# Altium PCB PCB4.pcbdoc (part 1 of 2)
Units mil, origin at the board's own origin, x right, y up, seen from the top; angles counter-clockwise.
Board outline 2271.98 x 2855.49 mil, 2 copper layers (Top Layer, Bottom Layer); 93 components, 70 nets, 333 pads, 163 vias.
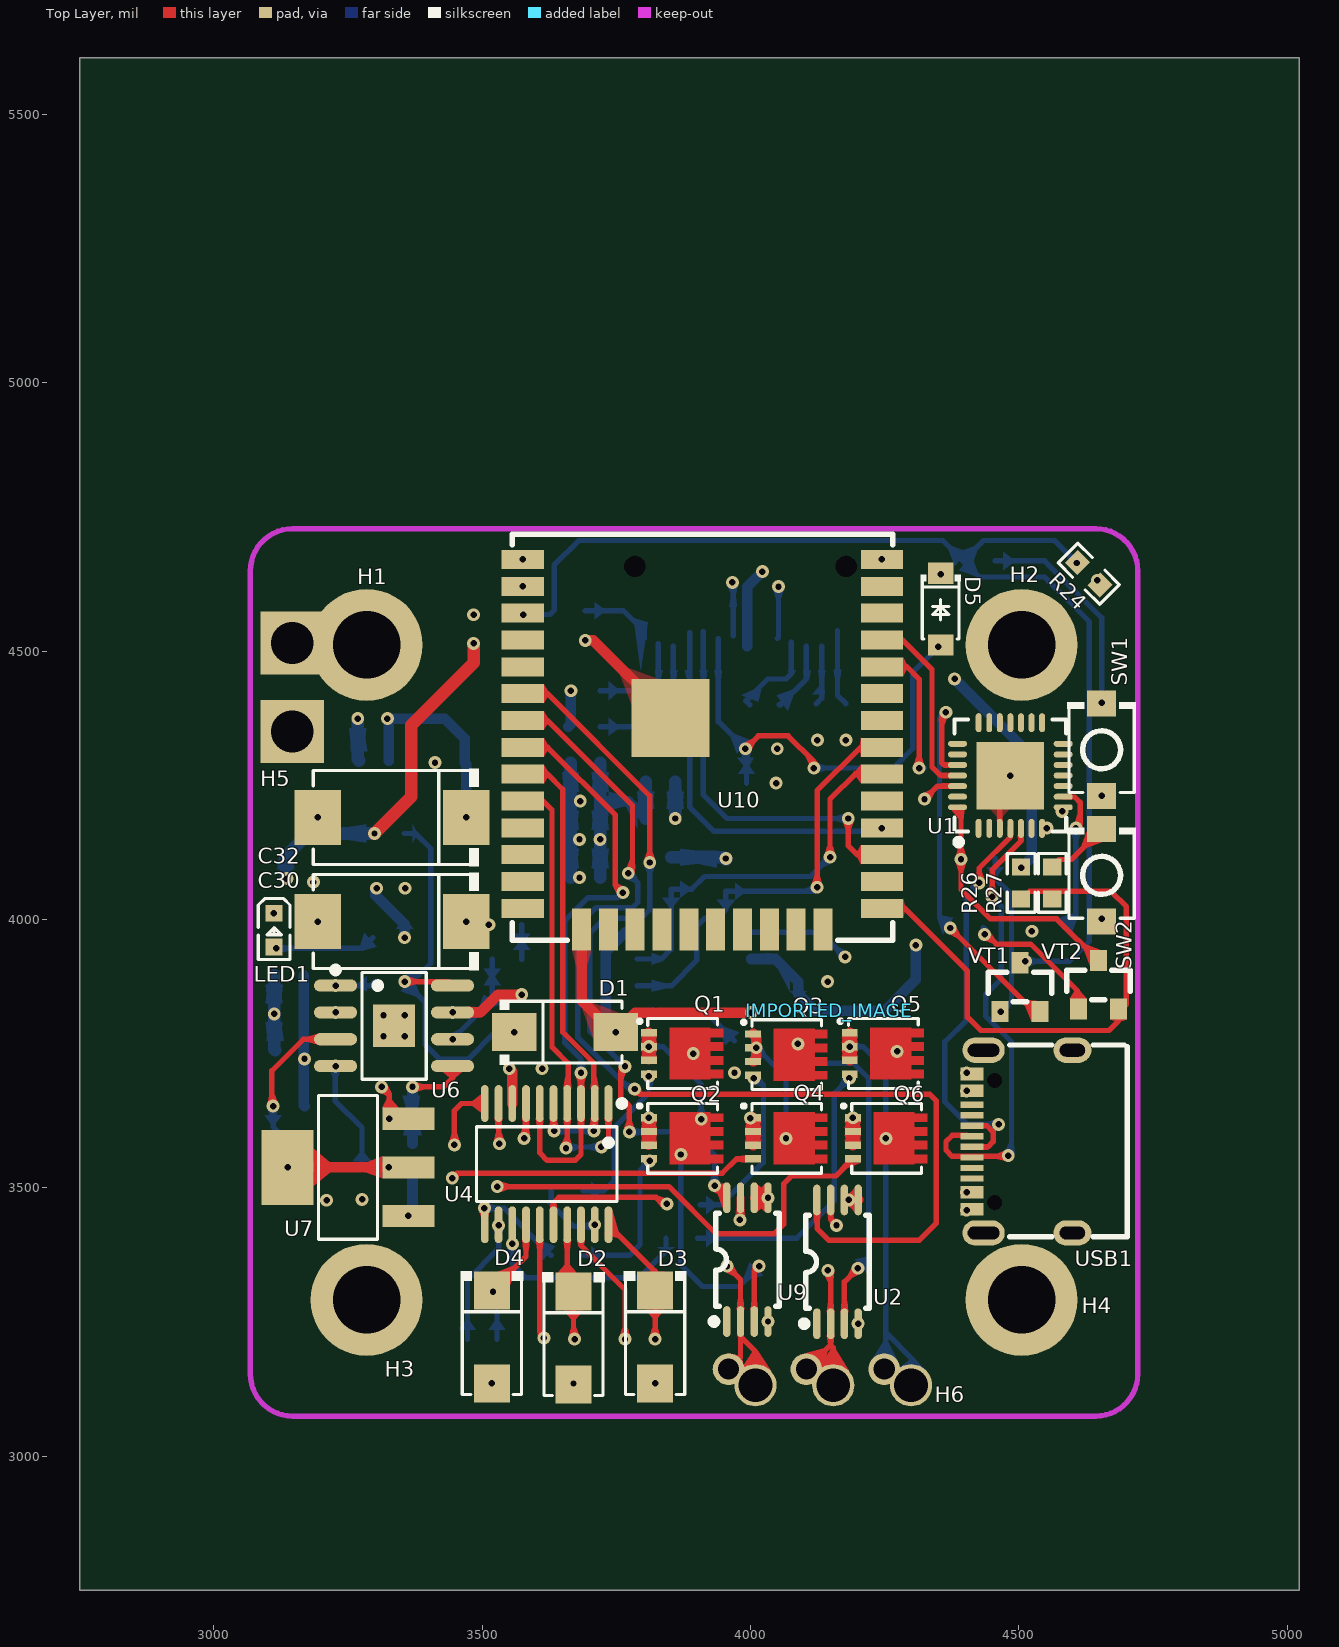
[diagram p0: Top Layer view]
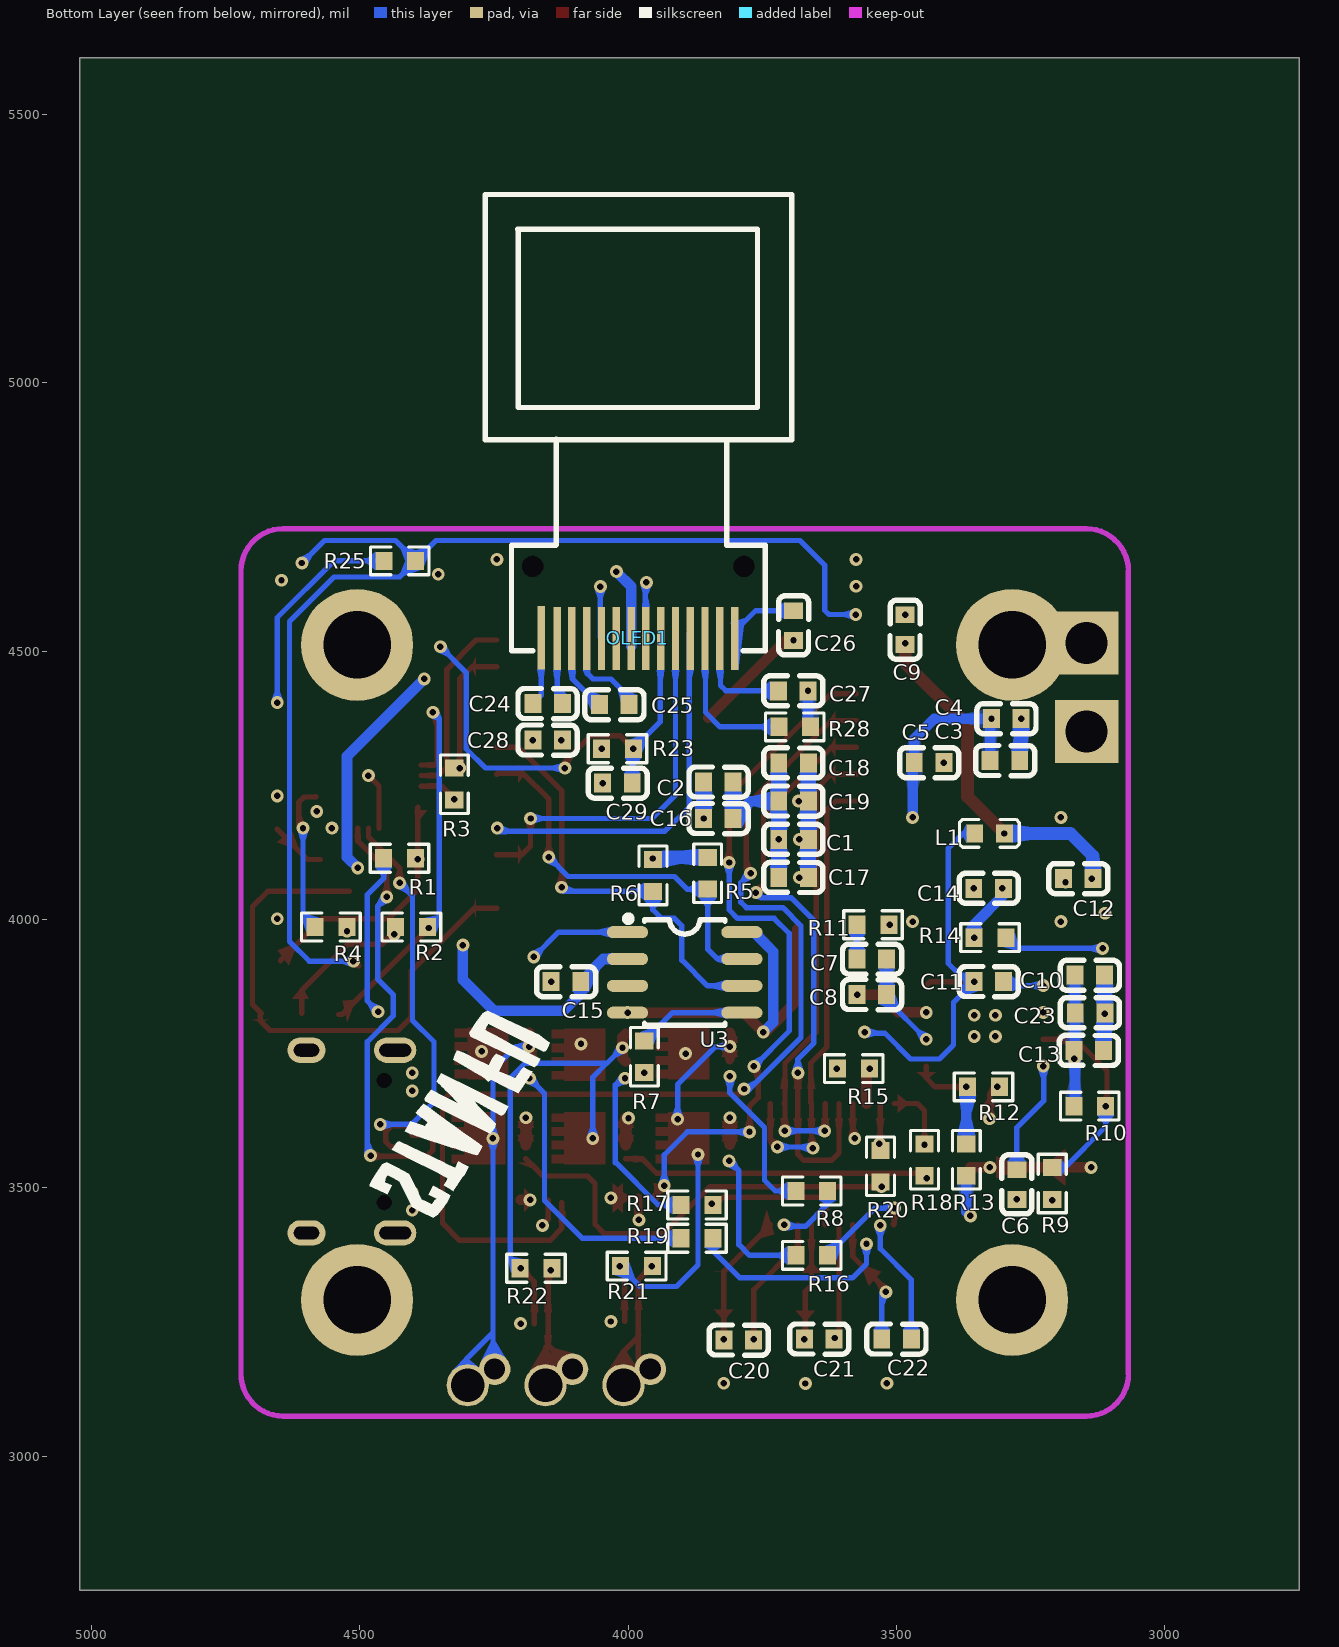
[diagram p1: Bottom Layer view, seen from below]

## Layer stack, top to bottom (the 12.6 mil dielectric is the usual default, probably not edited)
Top Layer: signal copper (thickness not stored)
Dielectric: dielectric 12.6, FR-4, Dk 4.8
Bottom Layer: signal copper (thickness not stored)

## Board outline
5021.98,2750 2750,2750 2750,5605.49 5021.98,5605.49

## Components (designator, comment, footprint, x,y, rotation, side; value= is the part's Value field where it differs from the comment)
C1 "0603B104K500NT_C30926" C0603 3692,4149.18 r180 bottom
C2 "0603B104K500NT_C30926" C0603 3832,4256 r0 bottom
C3 "CAP_0603" C0603 3298,4296 r0 bottom
C4 "CAP_0603" C0603 3295.56,4374 r0 bottom
C5 "CAP_0603" C0603 3439.56,4292 r0 bottom
C6 "CAP_0603" C0603 3276,3506 r270 bottom
C7 "CAP_0603" C0603 3546,3926 r0 bottom
C8 "CAP_0603" C0603 3546,3860 r0 bottom
C9 "CAP_0603" C0603 3484,4540 r90 bottom
C10 "CAP_0603" C0603 3140,3896 r0 bottom
C11 "CAP_0603" C0603 3328,3884 r180 bottom
C12 "CAP_0603" C0603 3161.56,4076 r0 bottom
C13 "CAP_0603" C0603 3142,3756 r0 bottom
C14 "CAP_0603" C0603 3328.61,4058 r0 bottom
C15 "CAP_0603" C0603 4116,3884 r0 bottom
C16 "0603B104K500NT_C30926" C0603 3832,4188 r0 bottom
C17 "0603B104K500NT_C30926" C0603 3692,4078 r180 bottom
C18 "0603B104K500NT_C30926" C0603 3692,4291.54 r180 bottom
C19 "0603B104K500NT_C30926" C0603 3692,4220.36 r180 bottom
C20 "CAP_0603" C0603 3794,3216 r180 bottom
C21 "CAP_0603" C0603 3644,3218 r180 bottom
C22 "CAP_0603" C0603 3500,3218 r180 bottom
C23 "CAP_0603" C0603 3139.56,3826 r180 bottom
C24 "CAP_0603" C0603 4150,4402 r180 bottom
C25 "CAP_0603" C0603 4026,4400 r0 bottom
C26 "CAP_0603" C0603 3692,4547.56 r270 bottom
C27 "CAP_0603" C0603 3692.61,4426 r0 bottom
C28 "CAP_0603" C0603 4150,4334 r180 bottom
C29 "CAP_0603" C0603 4020,4254 r0 bottom
C30 "TAJE107M025RNJ" CAP-SMD_L7.3-W4.3-R-RD 3332,3996 r0 top
C32 "TAJE107M025RNJ" CAP-SMD_L7.3-W4.3-R-RD 3332,4190 r0 top
D1 "SS34_C3014011" SMA_L4.3-W2.7-LS5.1-RD 3654,3790 r0 top
D2 "1N5819_C437199" SMA_L4.4-W2.6-LS5.0-RD 3670,3220 r270 top
D3 "1N5819_C437199" SMA_L4.4-W2.6-LS5.0-RD 3822,3222 r270 top
D4 "1N5819_C437199" SMA_L4.4-W2.6-LS5.0-RD 3518,3222 r270 top
D5 "1N4148W_C129869" SOD-123_L2.6-W1.8-LS3.7-RD 4354,4578 r270 top
H1 "M3定位孔" M3定位孔 3284.54,4511.46 r0 top
H2 "M3定位孔" M3定位孔 4505.01,4511.46 r0 top
H3 "M3定位孔" M3定位孔 3284.54,3290.99 r0 top
H4 "M3定位孔" M3定位孔 4505.01,3290.99 r0 top
H5 "Power Hole" "POWER IN" 3146,4350 r180 top
H6 "Motor Output Hole" "Motor Output Pin" 4008.92,3132.08 r90 top
IMPORTED_IMAGE "IMPORTED_IMAGE" IMPORTED_IMAGE 4146.34,3830.01 r0 top
L1 "L_0603" L0603 3326.81,4160 r180 bottom
LED1 "NCD0603R1_C84263" LED0603-RD_RED 3112,3980 r270 top
OLED1 "QG-6432TLBEG02" OLED-SMD_QG-6432TLBEG02 3982,4524 r270 bottom
Q1 "WSD3066DN33" DFN-8_L3.3-W3.3-P0.65-BL 3841.31,3750.09 r270 top
Q2 "WSD3066DN33" DFN-8_L3.3-W3.3-P0.65-BL 3841.31,3592.09 r270 top
Q3 "WSD3066DN33" DFN-8_L3.3-W3.3-P0.65-BL 4035.31,3748.09 r270 top
Q4 "WSD3066DN33" DFN-8_L3.3-W3.3-P0.65-BL 4035.31,3592.09 r270 top
Q5 "WSD3066DN33" DFN-8_L3.3-W3.3-P0.65-BL 4215.31,3750.09 r270 top
Q6 "WSD3066DN33" DFN-8_L3.3-W3.3-P0.65-BL 4221.31,3592.09 r270 top
R1 "0603WAF1002T5E" R0603 4426,4114 r0 bottom
R2 "0603WAF1002T5E" R0603 4404,3986 r0 bottom
R3 "0603WAF1002T5E" R0603 4324,4252 r270 bottom
R4 "0603WAF1002T5E" R0603 4554,3986 r0 bottom
R5 "0603WAF1002T5E" R0603 3852,4086 r270 bottom
R6 "0603WAF1002T5E" R0603 3954,4082 r270 bottom
R7 "0603WAF1002T5E" R0603 3970,3744 r270 bottom
R8 "0603WAF1002T5E" R0603 3658,3494 r180 bottom
R9 "Res_0603" R0603 3210,3508 r270 bottom
R10 "Res_0603" R0603 3140,3652 r180 bottom
R11 "Res_0603" R0603 3544,3990 r0 bottom
R12 "Res_0603" R0603 3338,3688 r180 bottom
R13 "Res_0603" R0603 3370,3552 r90 bottom
R14 "Res_0603" R0603 3325.81,3966 r180 bottom
R15 "Res_0603" R0603 3580,3722 r180 bottom
R16 "0603WAF1002T5E" R0603 3658,3374 r180 bottom
R17 "0603WAF1002T5E" R0603 3872,3468 r180 bottom
R18 "0603WAF1002T5E" R0603 3448,3552 r90 bottom
R19 "0603WAF1002T5E" R0603 3872,3406 r180 bottom
R20 "0603WAF1002T5E" R0603 3530,3540 r90 bottom
R21 "Res_0603" R0603 3984.34,3354 r0 bottom
R22 "Res_0603" R0603 4172,3350 r0 bottom
R23 "Res_0603" R0603 4020,4318 r0 bottom
R24 "Res_0603" R0603 4630,4644 r315 top
R25 "Res_0603" R0603 4425.66,4668 r180 bottom
R26 "Res_0603" R0603 4504,4068 r90 top
R27 "Res_0603" R0603 4562,4068 r270 top
R28 "Res_0603" R0603 3689.81,4358.77 r0 bottom
SW1 "TS-1088-AR02016" SW-SMD_L3.9-W3.0-P4.45 4654,4316 r90 top
SW2 "TS-1088-AR02016" SW-SMD_L3.9-W3.0-P4.45 4654,4082 r90 top
U1 "CP2102-GMR" WQFN-28_L5.0-W5.0-P0.50-BL-EP3.2 4484.01,4268.01 r0 top
U2 "INA240A2PWR" TSSOP-8_L4.4-W3.0-P0.65-LS6.4-BL 4162,3362 r0 top
U3 "AS5600-ASOT" SOIC-8_L5.0-W4.0-P1.27-LS6.0-BL 3894.77,3901.23 r270 bottom
U4 "EG2133_C190343" TSSOP-20_L6.5-W4.4-P0.65-LS6.4-BL 3620,3544 r180 top
U6 "TPS54331DDAR" SOIC-8_L5.0-W4.0-P1.27-LS6.0-BL-EP2.0 3335.68,3801.68 r270 top
U7 "AMS1117-3.3_C351785" SOT-223_L6.5-W3.5-P2.30-LS7.0-BR 3250,3538 r0 top
U9 "INA240A2PWR" TSSOP-8_L4.4-W3.0-P0.65-LS6.4-BL 3994,3366 r0 top
U10 "ESP32-WROOM-32U-H4" WIFI-SMD_ESP32-WROOM-32UE-A 3910,4326 r0 top
USB1 "TYPE-C 16PIN 2MD(073)" USB-C-SMD_TYPE-C-6PIN-2MD-073 4506,3586 r90 top
VT1 "S8050_C397180" SOT-23_L2.9-W1.3-P1.90-LS2.4-BR 4502,3874 r270 top
VT2 "S8050_C397180" SOT-23_L2.9-W1.3-P1.90-LS2.4-BR 4648,3878 r270 top

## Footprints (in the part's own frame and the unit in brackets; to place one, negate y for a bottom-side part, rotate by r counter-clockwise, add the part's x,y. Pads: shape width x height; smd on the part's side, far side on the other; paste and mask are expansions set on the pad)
C0603 [mm]
  rect 0.8x0.9 smd: 1(-0.7,0) 2(0.7,0)
  silkscreen extent -1.41,-0.71 1.39,0.72
CAP-SMD_L7.3-W4.3-R-RD [mil]
  rect 86.91x102.05 smd: 1(138.24,0) 2(-138.24,0)
  silkscreen extent -147,-91 162,91
DFN-8_L3.3-W3.3-P0.65-BL [mm]
  rect 0.35x0.75 smd: 1(-0.975,-0.78) 2(-0.325,-0.78) 3(0.325,-0.78) 4(0.975,-0.78)
  Top Layer region: -1.222,0.201 -1.222,2.129 -1.174,2.129 -1.174,2.73 -0.773,2.73 -0.773,2.129 -0.524,2.129 -0.524,2.73 -0.123,2.73 -0.123,2.129 0.126,2.129 0.126,2.73 0.528,2.73 0.528,2.129 0.777,2.129 0.777,2.73 0.777,2.129 0.777,2.73 1.178,2.73 1.178,2.129 1.226,2.129 1.226,0.201
  silkscreen extent -1.65,-1.27 1.65,2.46
IMPORTED_IMAGE [mil]
L0603 [mm]
  rect 0.8x0.864 smd: 1(-0.7,0) 2(0.7,0)
  silkscreen extent -1.42,-0.65 1.41,0.67
LED0603-RD_RED [mm]
  rect 0.8x0.8 smd: 1(-0.8,-0.003) 2(0.8,0.003)
  silkscreen extent -1.49,-0.75 1.39,0.76
M3定位孔 [mm]
  round 5.3 hole 3.2: 1(0,0)
"Motor Output Pin" [mm]
  round 2 hole 1.6: 1(0,0) 2(-0.002,-3.685) 3(-0.002,-7.368)
  round 1.5 hole 1: 1(0.762,1.27) 2(0.76,-2.415) 3(0.76,-6.098)
OLED-SMD_QG-6432TLBEG02 [mm]
  rect 3x0.35 smd: 1(-0.017,-4.577) 2(0.017,-3.823) 3(0.017,-3.122) 4(0.017,-2.423) 5(0.017,-1.722) 6(0.017,-1.024) 7(0.017,-0.323) 8(0.017,0.378) 9(0.017,1.077) 10(0.017,1.778) 11(0.017,2.476) 12(0.017,3.178) 13(0.017,3.879) 14(0.017,4.577)
  Multi-Layer board cut-out: -3.398,4.519 -3.614,4.569 -3.788,4.707 -3.885,4.908 -3.885,5.13 -3.788,5.331 -3.614,5.47 -3.398,5.519 -3.398,5.519 -3.181,5.47 -3.007,5.331 -2.91,5.13 -2.91,4.908 -3.007,4.707 -3.181,4.569 -3.398,4.519
  Multi-Layer board cut-out: -3.398,-5.481 -3.614,-5.431 -3.788,-5.293 -3.885,-5.092 -3.885,-4.87 -3.788,-4.669 -3.614,-4.53 -3.398,-4.481 -3.398,-4.481 -3.181,-4.53 -3.007,-4.669 -2.91,-4.87 -2.91,-5.092 -3.007,-5.293 -3.181,-5.431 -3.398,-5.481
  silkscreen extent -21,-7.22 0.6,7.28
"POWER IN" [mm]
  rect 3x3 hole 2: 1(0,0) 2(0,-4.191)
R0603 [mil]
  rect 31.75x34.02 smd: 1(-29.66,0) 2(29.66,0)
  silkscreen extent -55,-26 55,26
SMA_L4.3-W2.7-LS5.1-RD [mm]
  rect 2.1x1.8 smd: 1(-2.4,0) 2(2.4,0)
  silkscreen extent -3.08,-1.54 2.7,1.54
SMA_L4.4-W2.6-LS5.0-RD [mm]
  rect 1.8x1.7 smd: 1(-2.192,0) 2(2.192,0)
  silkscreen extent -3.11,-1.48 2.73,1.48
SOD-123_L2.6-W1.8-LS3.7-RD [mm]
  rect 1x1.2 smd: 1(-1.7,0) 2(1.7,0)
  silkscreen extent -1.63,-0.94 1.41,0.94
SOIC-8_L5.0-W4.0-P1.27-LS6.0-BL [mil]
  oval 22.38x76.78 smd: 1(-75,-106.5) 2(-25,-106.5) 3(25,-106.5) 4(75,-106.5) 5(75,106.5) 6(25,106.5) 7(-25,106.5) 8(-75,106.5)
  silkscreen extent -106,-111 98,75
SOIC-8_L5.0-W4.0-P1.27-LS6.0-BL-EP2.0 [mm]
  oval 0.574x2.038 smd: 1(-1.905,-2.769) 2(-0.635,-2.769) 3(0.635,-2.769) 4(1.905,-2.769) 5(1.905,2.769) 6(0.635,2.769) 7(-0.635,2.769) 8(-1.905,2.769)
  rect 2x2 smd: 9(0,0)
  silkscreen extent -2.79,-2.92 2.53,1.52
SOT-23_L2.9-W1.3-P1.90-LS2.4-BR [mm]
  rect 1x0.8 smd: 1(1.15,-0.95) 2(1.15,0.95) 3(-1.15,0)
  silkscreen extent -0.7,-1.5 0.7,1.5
SOT-223_L6.5-W3.5-P2.30-LS7.0-BR [mm]
  rect 2.465x1.05 smd: 1(2.857,-2.3) 2(2.857,0) 3(2.857,2.3)
  rect 2.465x3.54 smd: 4(-2.857,0)
  silkscreen extent -1.4,-3.4 1.4,3.4
SW-SMD_L3.9-W3.0-P4.45 [mm]
  rect 1.23x1.36 smd: 1(-2.185,0) 2(2.185,0)
  silkscreen extent -2.03,-1.62 2.25,1.62
TSSOP-8_L4.4-W3.0-P0.65-LS6.4-BL [mil]
  oval 13.9x57.24 smd: 1(-38.39,-115.24) 2(-12.79,-115.24) 3(12.8,-115.24) 4(38.39,-115.24) 5(38.39,115.24) 6(12.8,115.24) 7(-12.79,115.24) 8(-38.39,115.24)
  silkscreen extent -68,-121 59,87
TSSOP-20_L6.5-W4.4-P0.65-LS6.4-BL [mil]
  oval 14.33x68.58 smd: 1(-115.16,-113.03) 2(-89.57,-113.03) 3(-63.98,-113.03) 4(-38.39,-113.03) 5(-12.79,-113.03) 6(12.8,-113.03) 7(38.39,-113.03) 8(63.98,-113.03) 9(89.57,-113.03) 10(115.16,-113.03) 11(115.16,113.03) 12(89.57,113.03) 13(63.98,113.03) 14(38.39,113.03) 15(12.8,113.03) 16(-12.79,113.03) 17(-38.39,113.03) 18(-63.98,113.03) 19(-89.57,113.03) 20(-115.16,113.03)
  silkscreen extent -146,-119 131,70
USB-C-SMD_TYPE-C-6PIN-2MD-073 [mm]
  rect 0.6x1.1 smd: 1(-3.2,2.375) 2(-2.4,2.375) 11(2.4,2.375) 12(3.2,2.375)
  rect 0.3x1.1 smd: 3(-1.75,2.375) 4(-1.25,2.375) 5(-0.75,2.375) 6(-0.25,2.375) 7(0.25,2.375) 8(0.75,2.375) 9(1.25,2.375) 10(1.75,2.375)
  oval 1.2x1.8 hole 0.6 slot 1.2 at 90 deg: 13(-4.325,-2.375) 14(4.325,-2.375)
  oval 1.2x2 hole 0.6 slot 1.5 at 90 deg: 13(-4.325,1.825) 14(4.325,1.825)
  Multi-Layer board cut-out: -2.89,0.955 -2.738,0.99 -2.616,1.087 -2.549,1.227 -2.549,1.383 -2.616,1.523 -2.738,1.62 -2.89,1.655 -2.89,1.655 -3.042,1.62 -3.164,1.523 -3.231,1.383 -3.231,1.227 -3.164,1.087 -3.042,0.99 -2.89,0.955
  Multi-Layer board cut-out: 2.89,0.955 3.042,0.99 3.164,1.087 3.231,1.227 3.231,1.383 3.164,1.523 3.042,1.62 2.89,1.655 2.89,1.655 2.738,1.62 2.616,1.523 2.549,1.383 2.549,1.227 2.616,1.087 2.738,0.99 2.89,0.955
  silkscreen extent -4.5,-4.97 4.57,0.6
WIFI-SMD_ESP32-WROOM-32UE-A [mm]
  rect 2x0.9 smd: 1(-8.5,8.755) 2(-8.5,7.485) 3(-8.5,6.215) 4(-8.5,4.945) 5(-8.5,3.675) 6(-8.5,2.405) 7(-8.5,1.135) 8(-8.5,-0.135) 9(-8.5,-1.405) 10(-8.5,-2.675) 11(-8.5,-3.945) 12(-8.5,-5.215) 13(-8.5,-6.485) 14(-8.5,-7.755) 25(8.5,-7.755) 26(8.5,-6.485) 27(8.5,-5.215) 28(8.5,-3.945) 29(8.5,-2.675) 30(8.5,-1.405) 31(8.5,-0.135) 32(8.5,1.135) 33(8.5,2.405) 34(8.5,3.675) 35(8.5,4.945) 36(8.5,6.215) 37(8.5,7.485) 38(8.5,8.755)
  rect 0.9x2 smd: 15(-5.715,-8.755) 16(-4.445,-8.755) 17(-3.175,-8.755) 18(-1.905,-8.755) 19(-0.635,-8.755) 20(0.635,-8.755) 21(1.905,-8.755) 22(3.175,-8.755) 23(4.445,-8.755) 24(5.715,-8.755)
  rect 3.7x3.7 smd: 39(-1.5,1.255)
  silkscreen extent -9,-9.27 9.02,9.95
WQFN-28_L5.0-W5.0-P0.50-BL-EP3.2 [mm]
  oval 0.28x0.9 smd: 1(-1.501,-2.5) 2(-1.001,-2.5) 3(-0.501,-2.5) 4(0,-2.5) 5(0.5,-2.5) 6(1.001,-2.5) 7(1.501,-2.5) 15(1.501,2.5) 16(1.001,2.5) 17(0.5,2.5) 18(0,2.5) 19(-0.501,2.5) 20(-1.001,2.5) 21(-1.501,2.5)
  oval 0.9x0.28 smd: 8(2.5,-1.501) 9(2.5,-1.001) 10(2.5,-0.501) 11(2.5,0) 12(2.5,0.5) 13(2.5,1.001) 14(2.5,1.501) 22(-2.5,1.501) 23(-2.5,1.001) 24(-2.5,0.5) 25(-2.5,0) 26(-2.5,-0.501) 27(-2.5,-1.001) 28(-2.5,-1.501)
  rect 3.2x3.2 smd: 29(0,0)
  silkscreen extent -2.65,-3.3 2.65,2.65

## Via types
v1: diameter 24.02, hole 12.01, Top Layer to Bottom Layer, 159 vias
v2: diameter 24, hole 12, Top Layer to Bottom Layer, 4 vias

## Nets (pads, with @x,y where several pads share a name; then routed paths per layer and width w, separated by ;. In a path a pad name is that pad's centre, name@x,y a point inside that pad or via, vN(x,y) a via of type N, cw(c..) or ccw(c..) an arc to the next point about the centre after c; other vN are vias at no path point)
3V3: C14.1 C15.1 C28.2 D5.1 OLED1.5 OLED1.8 R14.1 R23.2 R24.2 R26.2 U2.5 U2.6 U3.2 U7.2 U7.4 U9.5 U9.6 U10.2 | length 1448.2
  Top Layer w15.75: U9.6@4006.8,3481.24 v1(4032.39,3481.24)
  Top Layer w19.68: v1(3137.5,3538) v1(3326,3538) U7.2@3362.5,3538 ; v1(4182.8,3477.24) U2.5@4200.39,3477.24
  Bottom Layer w10: v1(3966,4628) 3968,4626 OLED1.8@3968,4528.57 ; OLED1.5@4049.8,4523.35 4052,4525.55 v1(4052,4620)
  Bottom Layer w19.68: C14.1@3301.05,4058 3301.05,4044.95 3355.47,3990.53 v1(3355.47,3966) ; U3.2@4001.27,3926.23 4046.21,3926.23 C15.1@4088.44,3884 4088.44,3861.56 4120,3830 4250,3830 4308,3888 v1(4308,3952) ; v1(4380,4448) 4524,4304 4524,4116 v1(4504,4096)
  other v1: 3303.02,4058 4049.66,4318 4124.41,4334 3575.35,4620.69 4646,4632 4354,4643
$1N1528: R3.2 U1.26 | length 73.3
  Top Layer w10: v1(4324,4224) 4348.3,4248.3 U1.26@4385.58,4248.3
  Bottom Layer w10: R3.2@4324,4222.34 v1(4324,4224)
$1N3198: R7.1 U3.5 | length 203.5
  Bottom Layer w10: U3.5@3788.27,3826.23 3917.43,3826.23 R7.1@3970,3773.66
$1N4734: R4.2 U1.9 | length 280.5
  Top Layer w10: U1.9@4582.43,4228.6 4583.03,4228 4604,4228 4614,4218 4614,4178 v1(4606,4170)
  Bottom Layer w10: R4.2@4583.66,3986 4606,4008.34 v1(4606,4170)
$1N4826: R1.2 VT1.1 | length 308.6
  Top Layer w10: VT1.1@4464.6,3828.72 4465.32,3828 v1(4466,3828)
  Bottom Layer w10: R1.2@4455.66,4114 4455.66,4076.34 4486,4046 4486,3848 v1(4466,3828)
$1N5701: R2.2 VT2.1 | length 272.2
  Top Layer w10: v1(4436,3972) 4440,3972 4458,3954 4522,3954 4608.6,3867.4 VT2.1@4608.6,3824.72
  Bottom Layer w10: R2.2@4433.66,3984.67 4436,3982.33 v1(4436,3972)
$1N6924: Q1.4 R8.1 | length 287.1
  Bottom Layer w10: R8.1@3687.66,3494 3726,3494 3746,3514 3746,3612 3810.62,3676.62 v1(3810.62,3707.71)
$1N8426: R9.1 R10.2 U6.3 | length 379.4
  Top Layer w10: v1(3110.34,3652) 3108,3654.34 3108,3718 3166.68,3776.68 U6.3@3226.66,3776.68
  Bottom Layer w10: v1(3110.34,3652) 3110.34,3613.66 3186,3538 3209.66,3538 R9.1@3210,3537.66
$1N8699: C7.1 C8.1 U6.6 | length 179.9
  Bottom Layer w10: v1(3444.7,3776.68) 3518.44,3850.42 C8.1@3518.44,3860 C7.1@3518.44,3926
  other v1: 3444.7,3776.68 3444.7,3776.68
$1N8755: C7.2 R11.2 | length 64
  Bottom Layer w10: C7.2@3573.56,3926 3573.66,3926.1 R11.2@3573.66,3990
$1N8822: C6.1 U6.4 | length 214.1
  Bottom Layer w10: v1(3226.66,3726.68) 3226,3726.02 3226,3662 3276,3612 C6.1@3276,3533.56
$1N10503: C11.1 D1.1 L1.1 U6.8 | length 760.7
  Top Layer w10: v1(3355.56,3884) 3437.39,3884 U6.8@3444.7,3876.68
  Bottom Layer w10: L1.1@3354.37,4160 3376,4160 3404,4132 3404,3918.3 3381.7,3896 3367.56,3896 v1(3355.56,3884) 3394,3845.56 3394,3766 3420,3740 3474,3740 3522,3788 3557.51,3788 v1(3559.51,3790)
$1N10899: R12.1 R13.2 U6.5 | length 209.9
  Top Layer w10: v1(3370,3688) 3428,3688 3444.7,3704.7 U6.5@3444.7,3726.68
  Bottom Layer w19.68: R13.2@3370,3581.66 v1(3370,3688)
$1N10932: C11.2 U6.1 | length 76.8
  Bottom Layer w10: v1(3226.66,3876.68) 3293.12,3876.68 C11.2@3300.44,3884
$1N15151: LED1.2 R14.2 | length 193.3
  Top Layer w10: LED1.2@3112.14,3948.52 3114.66,3946 v1(3116,3946)
  Bottom Layer w10: v1(3116,3946) 3276.15,3946 R14.2@3296.15,3966
$1N18188: Q2.4 R16.1 | length 282.4
  Top Layer w10: Q2.4@3810.62,3553.71 3812,3552.33 v1(3812,3550)
  Bottom Layer w10: R16.1@3687.66,3374 3774,3374 3794,3394 3794,3532 v1(3812,3550)
$1N19387: Q3.4 R17.1 | length 317.9
  Top Layer w10: Q3.4@4004.62,3709.71 4006,3708.33 v1(4006,3704)
  Bottom Layer w10: R17.1@3905.66,3468 3944,3468 4022,3546 ; v1@4010,3704 4022,3692 ; 4024,3546 4024,3692
$1N19388: Q4.4 R18.1 | length 575.4
  Top Layer w10: v1(3444,3518) 3452.99,3526.99 3946.99,3526.99 3973.71,3553.71 Q4.4@4004.62,3553.71
$1N20050: Q5.4 R19.1 | length 522.9
  Bottom Layer w10: R19.1@3901.66,3406 4086,3406 4156,3476 4156,3676 v1(4184,3704)
$1N20051: Q6.4 R20.1 | length 801.5
  Top Layer w10: v1(3528,3502) 3848,3502 3936,3414 4044,3414 4062,3432 4062,3508 4076,3522 4158.91,3522 Q6.4@4190.62,3553.71
$1N24329: C20.2 U4.18 | length 249.1
  Top Layer w10: U4.18@3683.98,3430.97 3683.98,3392.02 3766,3310 v1(3766,3218)
  Bottom Layer w10: v1(3766,3218) 3766,3216.44 C20.2@3766.44,3216
$1N24400: C20.1 D3.1 U4.20 | length 251.1
  Top Layer w10: U4.20@3735.16,3430.97 3822,3344.13 D3.1@3822,3308.32 v1(3822,3218)
  Bottom Layer w10: C20.1@3821.56,3216 3822,3216.44 v1(3822,3218)
$1N24724: C21.1 D2.1 U4.17 | length 219
  Top Layer w10: U4.17@3658.39,3430.97 3658.39,3317.93 D2.1@3670,3306.32 3670,3220 v1(3672,3218)
  Bottom Layer w10: C21.1@3671.56,3218 v1(3672,3218)
$1N24794: C21.2 U4.15 | length 213.4
  Top Layer w10: U4.15@3607.2,3430.97 3607.2,3232.8 v1@3618,3222
  other v1: 3614.83,3220
$1N24865: C22.1 D4.1 U4.14 | length 243.3
  Top Layer w10: v1(3520,3306) 3518,3308 D4.1@3518,3308.32 3581.61,3371.93 U4.14@3581.61,3430.97
  Bottom Layer w10: v1(3520,3306) 3527.56,3298.44 C22.1@3527.56,3218
$1N25145: C22.2 U4.12 | length 235.8
  Bottom Layer w10: C22.2@3472.44,3218 3472.44,3328.44 3530.43,3386.43 v1(3530.43,3429.83)
$1N42514: C24.1 OLED1.1 | length 142.3
  Bottom Layer w10: OLED1.1@4162,4537.87 4162,4417.56 C24.1@4177.56,4402
$1N42661: C25.1 OLED1.4 | length 174.2
  Bottom Layer w10: C25.1@3998.44,4400 3991.22,4407.22 4032,4448 4066,4448 4076,4458 OLED1.4@4076,4516.14
$1N43028: C24.2 OLED1.2 | length 111.6
  Bottom Layer w10: C24.2@4122.44,4402 4132.44,4412 OLED1.2@4132.44,4509.48
$1N43106: C25.2 OLED1.3 | length 131
  Bottom Layer w10: C25.2@4053.56,4400 4056,4400 4104,4448 OLED1.3@4104,4508.64
$1N43184: C26.1 OLED1.14 | length 138.8
  Bottom Layer w10: C26.1@3692,4575.12 3762.88,4575.12 3801.8,4536.2 OLED1.14@3801.8,4523.35
$1N43261: C27.2 OLED1.13 | length 189.3
  Bottom Layer w10: C27.2@3720.17,4426 3818,4426 3828,4436 OLED1.13@3828,4513.34
$1N44189: OLED1.12 R28.2 | length 270.5
  Bottom Layer w10: R28.2@3719.47,4358.77 3828.77,4358.77 3856,4386 OLED1.12@3856,4508.64
$1N60145: R25.1 SW1.2 | length 402.6
  Top Layer w10: SW1.2@4654,4402.02 v1(4654,4404)
  Bottom Layer w10: R25.1@4455.32,4668 4548,4668 4654,4562 v1(4654,4404)
$1N61799: R27.1 SW2.2 | length 103.3
  Top Layer w10: R27.1@4574,4111.66 4597.64,4111.66 SW2.2@4654,4168.02
AGND: C1.1 C2.1 C16.1 C17.1 C18.1 C19.1 Q2.1 Q2.2 Q2.3 Q4.1 Q4.2 Q4.3 Q6.1 Q6.2 Q6.3 R15.1 | length 532.9
  Top Layer w19.68: Q2.3@3810.62,3579.79 Q2.2@3810.62,3604.89 v1(3810.62,3630.48) ; Q4.3@4004.62,3579.3 Q4.2@4004.62,3604.89 Q4.1@4004.62,3630.48 ; Q6.3@4190.62,3579.3 Q6.2@4190.62,3604.89 v1(4190.62,3630.48)
  Bottom Layer w19.68: C19.1@3719.56,4220.36 3772.08,4220.36 C16.1@3804.44,4188
  Bottom Layer w23.62: C17.1@3719.56,4078 v1(3719.56,4149.18) C19.1@3719.56,4220.36 C18.1@3719.56,4291.54 ; C16.1@3804.44,4188 C2.1@3804.44,4256
  other v1: 3999.51,3629.89 3611.5,3722
AS5600_SCL: R5.2 U3.7 U10.30 | length 728.9
  Top Layer w10: v1(4148,4116) 4148,4224 4196,4272 4243.34,4272 U10.30@4244.65,4270.69
  Bottom Layer w10: U3.7@3788.27,3926.23 3833.66,3926.23 3852,3944.57 R5.2@3852,4056.34 3890.34,4056.34 3914,4080 4112,4080 v1(4148,4116)
AS5600_SDA: R6.2 U3.6 U10.31 | length 803.5
  Top Layer w10: v1(4124,4060) 4124,4240 4204.69,4320.69 U10.31@4244.65,4320.69
  Bottom Layer w10: U3.6@3788.27,3876.23 3852.23,3876.23 3900,3924 3900,3988 3914,4002 3938,4002 3954,4018 R6.2@3954,4052.34 4116.34,4052.34 v1(4124,4060)
CP_RX: U1.25 U10.35 | length 352.2
  Top Layer w10: U10.35@4244.65,4520.69 4283.31,4520.69 4338,4466 4338,4284 4354,4268 U1.25@4385.58,4268
CP_TX: R3.1 U10.34 | length 254.7
  Top Layer w10: U10.34@4244.65,4470.69 4291.02,4470.69 4314,4447.7 v1(4314,4282)
  Bottom Layer w10: v1(4314,4282) 4314.34,4281.66 R3.1@4324,4281.66
DTR: R1.1 U1.28 VT2.3 | length 464.1
  Top Layer w10: U1.28@4391.58,4208.9 4392,4208.48 v1(4392,4112) 4392,4056 4446.99,4001.01 4570.27,4001.01 VT2.3@4648,3923.28
ESP32_BOOT: R26.1 R27.2 U10.25 VT2.2 | length 1004.8
  Top Layer w10: U10.25@4244.65,4020.68 4287.31,4020.68 4404,3904 4404,3818 4429.1,3792.9 4667.72,3792.9 4685.4,3810.58 VT2.2@4685.4,3824.72 ; R26.1@4520,4052.34 4574,4052.34 4671.66,4052.34 4700,4024 4700,3841.32 VT2.2@4683.4,3824.72
ESP32_EN: R24.1 R25.2 U10.3 VT1.3 | length 2215.9
  Top Layer w10: U10.3@3575.35,4570.69 3575.35,4568.65 v1(3576,4568) ; VT1.3@4502,3913.28 4503.28,3913.28 v1(4512,3922)
  Bottom Layer w10: v1(3576,4568) 3626,4568 3634,4576 3634,4660 3680,4706 4358,4706 R25.2@4396,4668 ; v1(4512,3922) 4594,3922 4630.99,3958.99 4630.99,4555.01 4548,4638 4426,4638 R25.2@4396,4668 ; v1(4608,4664) 4566,4706 4434,4706 R25.2@4396,4668
GND: C3.2 C4.2 C5.2 C6.2 C8.2 C9.2 C10.2 C12.2 C13.2 C14.2 C15.2 C23.1 C26.2 C27.1 C28.1 C29.2 C30.1 C32.1 D1.2 H1.1 H2.1 H3.1 H4.1 H5.2 LED1.1 OLED1.7 R7.2 R10.1 R11.1 R13.1 R15.2 R28.1 SW1.1 SW2.1 U1.3 U1.29 U2.4 U2.7 U3.4 U3.8 U4.8 U6.7 U6.9 U7.1 U9.4 U9.7 U10.1 U10.15 U10.38 U10.39 USB1.1 USB1.12 USB1.13 USB1.14 | length 2275.8
  Top Layer w10: U2.7@4149.21,3477.24 4149.21,3441.62 4160,3430.83 v1(4160,3430) ; U1.3@4464.3,4169.58 4464.3,4248.3 v1(4484,4268)
  Top Layer w15.75: v1(3980,3440) 3981.21,3441.21 U9.7@3981.21,3481.24
  Top Layer w19.68: v1(3444.7,3826.68) 3496.67,3826.68 3529.98,3860 v1(3573.56,3860) ; v1(3550.34,3722) 3556.02,3716.32 U4.8@3556.02,3657.03 ; U10.15@3685,3981.32 3685,3849 3744,3790 v1(3748.49,3790) 3784.72,3826.23 v1(4001.27,3826.23) ; v1(3692,4520) 3706.36,4520 U10.39@3850.95,4375.41
  Bottom Layer w19.68: C10.2@3167.56,3896 3167.56,3654.1 R10.1@3169.66,3652 ; v1(3323.12,4374) C4.2@3325.56,4371.56 ; C3.2@3325.56,4296 C4.2@3325.56,4371.56 ; v1(3362.5,3447.45) 3370,3454.95 R13.1@3370,3522.34 ; v1(3470.24,4190) 3470.24,4288.88 C5.2@3467.12,4292 3467.12,4336.88 3430,4374 3328,4374 C4.2@3325.56,4371.56 ; R28.1@3660.15,4358.77 3665.05,4363.67 v1(3665.05,4426) ; v1(3748.49,3790) 3730,3808.49 3730,3940 3766.23,3976.23 U3.8@3788.27,3976.23 ; OLED1.7@3994,4508.84 3994,4620 v1(4022,4648)
  other v1: 4200.39,3246.76 4032.39,3250.76 4402.49,3458.01 3276,3478.44 3970,3714.34 4402.49,3713.99 3168.78,3740.06 4143.56,3884 3512.5,3990 3470.24,3996 4654,4001.29 3111.87,4011.48 3356.17,4058 3185.3,4069.33 4654,4229.98 4047.56,4254 4177.56,4334 3484,4567.56 3575.35,4670.69 4244.65,4670.69
M0_EN: U10.11
M0_GH1: R8.2 U4.19 | length 124.1
  Bottom Layer w10: R8.2@3628.34,3494 3628.34,3469.66 3670,3428 3706.6,3428 v1(3709.57,3430.97)
M0_GH2: R17.2 U4.16 | length 264
  Top Layer w10: U4.16@3632.79,3430.97 3632.79,3472 3642.79,3482 3824,3482 3836,3470 v1(3844,3470)
  Bottom Layer w10: R17.2@3842.34,3468 3844,3469.66 v1(3844,3470)
M0_GH3: R19.2 U4.13 | length 378.9
  Bottom Layer w10: v1(3556.02,3395.33) 3556.02,3358.02 3582,3332 3792,3332 3842.34,3382.34 R19.2@3842.34,3406
M0_GL1: R16.2 U4.11 | length 193.1
  Top Layer w10: v1(3504,3462) 3504,3434.13 3506,3432.13 U4.11@3504.84,3430.97
  Bottom Layer w10: v1(3504,3462) 3540.34,3462 R16.2@3628.34,3374
M0_GL2: R18.2 U4.10 | length 127.9
  Top Layer w10: v1(3448,3580) 3448,3644 3461.03,3657.03 U4.10@3504.84,3657.03
  Bottom Layer w10: v1(3448,3580) R18.2@3448,3581.66
M0_GL3: R20.2 U4.9 | length 77.8
  Top Layer w10: U4.9@3530.43,3657.03 3530.43,3583.57 v1(3532,3582)
  Bottom Layer w10: R20.2@3530,3581.66 3531.66,3581.66 v1(3532,3582)
M0_IN1: U4.1 U4.4 U10.10 | length 859
  Top Layer w10: U10.10@3575.35,4220.69 3613.32,4220.69 3630,4204 3630,3762 3660,3732 3660,3658.64 U4.4@3658.39,3657.03 3658.39,3576.39 v1(3656,3574) ; v1(3722,3576) 3735.16,3589.16 U4.1@3735.16,3657.03
  Bottom Layer w10: v1(3656,3574) 3658,3576 v1(3722,3576)
M0_IN2: U4.2 U4.5 U10.9 | length 873.9
  Top Layer w10: U10.9@3575.35,4270.69 3621.72,4270.69 3650,4242.4 3650,3790 3708,3732 3708,3658.6 U4.2@3709.57,3657.03 3708,3655.46 v1(3708,3606) ; U4.5@3632.79,3657.03 3632.79,3606.79 3633.58,3606 v1(3634,3606)
  Bottom Layer w10: v1(3634,3606) v1(3708,3606)
M0_IN3: U4.3 U4.6 U10.8 | length 1132.4
  Top Layer w10: U10.8@3575.35,4320.69 3621.72,4320.69 3748,4194.4 3748,4064 v1(3762,4050) ; U4.6@3607.2,3657.03 3607.2,3564.8 3621.01,3550.99 3672.99,3550.99 3683.98,3561.98 U4.3@3683.98,3657.03 v1(3684,3714)
  Bottom Layer w10: v1(3684,3714) 3684,3740 3654,3770 3654,3998 3696,4040 3752,4040 v1(3762,4050)
M0_OUT1_CS: U9.8 U10.6 | length 1331.3
  Top Layer w10: U10.6@3575.35,4420.69 3621.72,4420.69 3812,4230.4 v1(3812,4106) ; v1(3766,3726) 3758,3718 3758,3668 3774,3652 v1(3774,3604) ; v1(3932.85,3504) U9.8@3955.61,3481.24
  Bottom Layer w10: v1(3766,3726) 3700,3792 3700,3974 3728,4002 3796,4002 3812,4018 v1(3812,4106) ; v1(3774,3604) 3890,3604 3932.85,3561.15 v1(3932.85,3504)
M0_OUT1_N: H6.1 R21.1 U9.2 | length 315
  Top Layer w10: v1(3956,3354) 3981.21,3328.79 U9.2@3981.21,3250.76 U9.2@3981.21,3222.73 ; H6.1@3958.92,3162.08 3981.21,3184.37 U9.2@3981.21,3222.73 ; H6.1@4008.92,3132.08 4008.92,3195.01 U9.2@3981.21,3222.73
  Bottom Layer w10: R21.1@3954.68,3354 v1(3956,3354)
M0_OUT1_P: Q1.1 Q1.2 Q1.3 R21.2 U9.3 | length 735.3
  Top Layer w10: U9.3@4006.8,3250.76 4006.8,3344.8 v1(4016,3354)
  Top Layer w15.75: Q1.3@3810.62,3737.3 v1(3810.62,3762.89)
  Top Layer w19.68: v1(3810.62,3762.89) Q1.1@3810.62,3788.48
  Bottom Layer w10: v1(3810.62,3762.89) 3837.11,3762.89 3908,3692 v1(3908,3628) ; v1(3870,3562) 3870,3356 3910,3316 3978,3316 v1(4016,3354) R21.2@4014,3354
M0_OUT2_CS: U2.8 U10.7 | length 2036.9
  Top Layer w10: U10.7@3575.35,4370.69 3621.72,4370.69 3780,4212.4 3780,4094 v1(3772,4086) ; v1(3784,3684) 3794,3674 4334,3674 4346,3662 4346,3434 4314,3402 4146,3402 4124,3424 U2.8@4124,3472
  Bottom Layer w10: v1(3772,4086) 3790,4068 3790,4032 3780,4022 3712,4022 3678,3988 3678,3780 3774,3684 v1(3784,3684)
M0_OUT2_N: H6.2 R22.1 U2.2 | length 286.8
  Top Layer w10: H6.2@4104,3162 4149.21,3207.21 ; v1(4144,3346) 4149.21,3340.79 U2.2@4149.21,3246.76 4149.21,3207.21 ; H6.2@4154,3132 4154,3202.42 4149.21,3207.21
  Bottom Layer w10: R22.1@4142.34,3350 4142.34,3347.66 v1(4144,3346)
M0_OUT2_P: Q3.1 Q3.2 Q3.3 R22.2 U2.3 | length 916.8
  Top Layer w10: U2.3@4174.8,3246.76 4174.8,3324.8 v1(4200,3350)
  Top Layer w19.68: Q3.3@4004.62,3735.3 4010.62,3741.3 v1(4010.62,3760.89) 4010.62,3780.48 Q3.1@4004.62,3786.48
  Bottom Layer w10: v1(4010.62,3760.89) 4039.51,3732 4040,3732 ; v1(4066,3592) 4066,3706 4040,3732 ; v1(4200,3350) R22.2@4201.66,3350 4220,3368.34 4220,3704 4192,3732 4040,3732
M0_OUT3: H6.3 Q5.1 Q5.2 Q5.3 | length 815.5
  Top Layer w19.68: Q5.3@4184.62,3737.3 v1(4184.62,3762.89) Q5.1@4184.62,3788.48
  Bottom Layer w10: v1(4184.62,3762.89) 4209.11,3762.89 4252,3720 v1(4252,3592) 4252,3230 ; H6.3@4249,3162 4252,3165 4252,3230 ; H6.3@4299,3132 4302,3135 4302,3180 4252,3230
OLED_RES: C29.1 D5.2 OLED1.9 R23.1 | length 869.5
  Top Layer w10: v1(3990.34,4318) 4014.34,4342 4070,4342 4118,4294 v1(4118,4282)
  Bottom Layer w10: OLED1.9@3939.6,4523.35 3940,4522.95 3940,4368.34 v1(3990.34,4318) 3992.44,4315.9 C29.1@3992.44,4254 ; v1(4118,4282) 4266,4282 4302,4318 4302,4460 v1(4350,4508)
OLED_SCL: OLED1.10 U10.27 | length 713
  Top Layer w10: v1(4182,4188) 4182,4136.97 4198.28,4120.69 U10.27@4244.65,4120.69
  Bottom Layer w10: OLED1.10@3912,4536.37 3912,4232 3956,4188 v1(4182,4188)
OLED_SDA: OLED1.11 U10.28 | length 704.9
  Top Layer w10: v1(4244,4170) U10.28@4244.65,4170.65
  Bottom Layer w10: OLED1.11@3886.31,4534.57 3886.31,4209.69 3932,4164 4238,4164 v1(4244,4170)
RTS: R2.1 U1.24 VT1.2 | length 784.3
  Top Layer w10: v1(4364,4386) 4358,4386 4356,4384 4356,4292 4360.3,4287.7 U1.24@4385.58,4287.7 ; v1(4372,3984) 4533.28,3822.72 VT1.2@4539.4,3822.72
  Bottom Layer w10: v1(4364,4386) 4352,4374 4352,4004 v1(4372,3984) 4373.67,3984 R2.1@4374.34,3984.67
USB-PWR-DM: U1.5 USB1.5 USB1.7 | length 854.1
  Top Layer w10: USB1.7@4402.49,3597.84 4375.85,3597.84 4364,3586 4364,3570 4375.52,3558.47 4478.48,3558.47 v1(4480,3560) ; v1(4450,4042) 4450,4092.1 4503.7,4145.8 U1.5@4503.7,4169.58
  Bottom Layer w10: v1(4450,4042) 4467.01,4024.99 4467.01,3889.01 4438,3860 4438,3820 4486,3772 4486,3566 v1(4480,3560)
USB-PWR-DP: U1.4 USB1.6 USB1.8 | length 783.4
  Top Layer w10: USB1.6@4412.49,3576.16 4442.15,3576.16 4452,3586 4452,3604 4440.48,3615.53 USB1.8@4412.49,3615.53 ; v1(4426,4068) 4426,4095.72 4484,4153.72 U1.4@4484,4169.58
  Bottom Layer w10: v1(4426,4068) 4402,4044 4402,3812 4362,3772 4362,3660 4404,3618 v1(4462,3618)
VDD_5V: C9.1 C10.1 C12.1 C13.1 C23.2 D2.2 D3.2 D4.2 L1.2 R4.1 R5.1 R6.1 R12.2 U1.7 U1.8 U3.1 U4.7 U7.3 USB1.2 USB1.11 | length 1225.8
  Top Layer w10: v1(3312.41,3688) 3326.5,3673.91 v1(3326.5,3628.55) ; v1(3578,3592) 3581.61,3595.61 U4.7@3581.61,3657.03
  Top Layer w23.62: v1(3299.26,4160) 3368,4228.74 3368,4362 3484,4478 v1(3484,4514.41)
  Bottom Layer w10: U3.1@4001.27,3976.23 4129.77,3976.23 v1(4176,3930)
  Bottom Layer w23.62: C10.1@3112.44,3896 v1(3112.44,3823.83) 3112.44,3758 C13.1@3114.44,3756 ; C12.1@3134,4076 3134,4118 3176,4160 v1(3299.26,4160) ; R5.1@3852,4115.66 3950,4115.66 R6.1@3954,4111.66
  other v1: 3670,3135.23 3518,3135.68 3822,3135.68 4402.49,3491.51 4402.49,3680.49 4524,3978 3135.97,4076 3954,4113.5 4552,4170 4580.43,4201.36
VIN: C1.2 C2.2 C3.1 C4.1 C5.1 C16.2 C17.2 C18.2 C19.2 C30.2 C32.2 H5.1 R9.2 U6.2 | length 360.5
  Bottom Layer w23.62: v1(3268,4374) 3268,4298.44 C3.1@3270.44,4296 ; C17.2@3664.44,4078 C1.2@3664.44,4149.18 C19.2@3664.44,4220.36 C18.2@3664.44,4291.54 ; v1(3859.56,4188) C2.2@3859.56,4256
  other v1: 3210,3476.7 3893.1,3750.02 4273.1,3754.02 4088,3768 3226.66,3826.68 3193.76,3996 3681.19,4078 3681.19,4149.18 3193.76,4190 3682.65,4220.46 3412,4292
"": OLED1.6 U1.1 U1.2 U1.6 U1.10 U1.11 U1.12 U1.13 U1.14 U1.15 U1.16 U1.17 U1.18 U1.19 U1.20 U1.21 U1.22 U1.23 U1.27 U2.1 U3.3 U9.1 U10.4 U10.5 U10.12 U10.13 U10.14 U10.16 U10.17 U10.18 U10.19 U10.20 U10.21 U10.22 U10.23 U10.24 U10.26 U10.29 U10.32 U10.33 U10.36 U10.37 USB1.3 USB1.4 USB1.9 USB1.10
  other v2: 3316,3782 3355.37,3782 3316,3821.37 3355.37,3821.37

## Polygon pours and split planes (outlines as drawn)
GND on Top Layer (solid, remove dead copper, pour order 0): 3055.99,3062.02 4771.98,3062.02 4771.98,4732.02 3055.99,4732.02
GND on Bottom Layer (solid, remove dead copper, pour order 1): 3053.98,3060 4741.98,3060 4741.98,4727.99 3053.98,4727.99
VIN on Inner1 (split plane): 3146,4355 3215.26,4355 3215.26,4345 3146,4345
VIN on Inner1 (split plane): 3151,4350 3151,4280.74 3141,4280.74 3141,4350
VIN on Inner1 (split plane): 3141,4350 3141,4419.26 3151,4419.26 3151,4350
GND on Inner2 (split plane): 4604.51,3415.72 4604.51,3381.9 4594.51,3381.9 4594.51,3415.72
GND on Inner2 (split plane): 4594.51,3415.72 4594.51,3449.55 4604.51,3449.55 4604.51,3415.72
GND on Inner2 (split plane): 4553.87,3420.72 4599.51,3420.72 4599.51,3410.72 4553.87,3410.72
GND on Inner2 (split plane): 4599.51,3420.72 4645.14,3420.72 4645.14,3410.72 4599.51,3410.72
GND on Inner2 (split plane): 3141,4445.74 3141,4515 3151,4515 3151,4445.74
GND on Inner2 (split plane): 3141,4515 3141,4584.26 3151,4584.26 3151,4515
GND on Inner2 (split plane): 3284.54,4516.46 3399.07,4516.46 3399.07,4506.46 3284.54,4506.46
GND on Inner2 (split plane): 3279.54,4511.46 3279.54,4626 3289.54,4626 3289.54,4511.46
GND on Inner2 (split plane): 3289.54,4511.46 3289.54,4396.93 3279.54,4396.93 3279.54,4511.46
GND on Inner2 (split plane): 4604.51,3756.28 4604.51,3722.45 4594.51,3722.45 4594.51,3756.28
GND on Inner2 (split plane): 4594.51,3756.28 4594.51,3790.1 4604.51,3790.1 4604.51,3756.28
GND on Inner2 (split plane): 4553.87,3761.28 4599.51,3761.28 4599.51,3751.28 4553.87,3751.28
GND on Inner2 (split plane): 4599.51,3761.28 4645.14,3761.28 4645.14,3751.28 4599.51,3751.28
GND on Inner2 (split plane): 4439.15,3756.28 4439.15,3722.45 4429.15,3722.45 4429.15,3756.28
GND on Inner2 (split plane): 4429.15,3756.28 4429.15,3790.1 4439.15,3790.1 4439.15,3756.28
GND on Inner2 (split plane): 4384.57,3761.28 4434.15,3761.28 4434.15,3751.28 4384.57,3751.28
GND on Inner2 (split plane): 4434.15,3761.28 4483.72,3761.28 4483.72,3751.28 4434.15,3751.28
GND on Inner2 (split plane): 4439.15,3415.72 4439.15,3381.9 4429.15,3381.9 4429.15,3415.72
GND on Inner2 (split plane): 4429.15,3415.72 4429.15,3449.55 4439.15,3449.55 4439.15,3415.72
GND on Inner2 (split plane): 4384.57,3420.72 4434.15,3420.72 4434.15,3410.72 4384.57,3410.72
GND on Inner2 (split plane): 4434.15,3420.72 4483.72,3420.72 4483.72,3410.72 4434.15,3410.72
GND on Inner2 (split plane): 4390.48,3295.99 4505.01,3295.99 4505.01,3285.99 4390.48,3285.99
GND on Inner2 (split plane): 4505.01,3295.99 4619.54,3295.99 4619.54,3285.99 4505.01,3285.99
GND on Inner2 (split plane): 4500.01,3290.99 4500.01,3405.52 4510.01,3405.52 4510.01,3290.99
GND on Inner2 (split plane): 4510.01,3290.99 4510.01,3176.46 4500.01,3176.46 4500.01,3290.99
GND on Inner2 (split plane): 3170,3295.99 3284.54,3295.99 3284.54,3285.99 3170,3285.99
GND on Inner2 (split plane): 3284.54,3295.99 3399.07,3295.99 3399.07,3285.99 3284.54,3285.99
GND on Inner2 (split plane): 3279.54,3290.99 3279.54,3405.52 3289.54,3405.52 3289.54,3290.99
GND on Inner2 (split plane): 3289.54,3290.99 3289.54,3176.46 3279.54,3176.46 3279.54,3290.99
GND on Inner2 (split plane): 4390.48,4516.46 4505.01,4516.46 4505.01,4506.46 4390.48,4506.46
GND on Inner2 (split plane): 4505.01,4516.46 4619.54,4516.46 4619.54,4506.46 4505.01,4506.46
GND on Inner2 (split plane): 4500.01,4511.46 4500.01,4626 4510.01,4626 4510.01,4511.46
GND on Inner2 (split plane): 4510.01,4511.46 4510.01,4396.93 4500.01,4396.93 4500.01,4511.46

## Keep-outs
Board Outline Layer:
  lines w10 net "": 3068,3153.2 3068,4649.26 cw(c3146.74,4649.26) 3146.74,4728 4642.8,4728 cw(c4642.8,4649.26) 4721.54,4649.26 4721.54,3153.2 cw(c4642.8,3153.2) 4642.8,3074.46 3146.74,3074.46 cw(c3146.74,3153.2) 3068,3153.2

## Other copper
Top Layer:
  region net DTR: 4387,4188.39 4397,4188.39 4397.78,4203.39 4374.5,4203.39
  region net $1N1528: 4356.06,4243.3 4373.38,4242.79 4373.38,4253.81 4356.06,4253.3
  region net CP_RX: 4356.06,4263 4373.38,4262.49 4373.38,4273.51 4356.06,4273
  region net RTS: 4360.3,4282.7 4373.38,4282.19 4373.38,4293.21 4360.3,4292.7
  region net USB-PWR-DM: 4508.7,4145.8 4509.21,4157.38 4498.19,4157.38 4498.7,4145.8
  region net RTS: 4513.05,3850.02 4513.05,3835.88 4523.65,3809.04 4532.34,3848.41
  region net ESP32_BOOT: 4680.4,3810.58 4690.4,3810.58 4701.15,3813.04 4669.65,3813.04
  region net DTR: 4621.65,3942.56 4632.25,3914.28 4653.07,3942.96 4624.78,3953.57
  region net $1N5701: 4603.6,3867.4 4594.85,3852.41 4626.1,3852.41 4613.6,3867.4
  region net M0_OUT1_P: 3818.49,3762.89 3802.75,3762.89 3795.86,3744.19 3825.38,3744.19
  region net M0_OUT1_P: 3818.49,3737.3 3825.38,3756 3795.86,3756 3802.75,3737.3
  region net M0_OUT1_P: 3820.46,3788.48 3800.78,3788.48 3795.86,3769.78 3825.38,3769.78
  region net M0_OUT1_P: 3820.46,3762.89 3825.38,3781.59 3795.86,3781.59 3800.78,3762.89
  region net M0_IN1: 3730.16,3609.77 3740.16,3609.77 3742.33,3629.9 3727.99,3629.9
  region net M0_IN2: 3703,3612.04 3713,3608.61 3716.74,3629.9 3702.4,3629.9
  region net M0_IN2: 3703,3702.02 3702.4,3684.16 3716.74,3684.16 3713,3705.45
  region net M0_IN3: 3678.98,3609.77 3688.98,3609.77 3691.15,3629.9 3676.81,3629.9
  region net M0_IN3: 3689,3704.27 3679,3704.31 3676.81,3684.16 3691.15,3684.16
  region net M0_IN1: 3653.39,3609.77 3663.39,3609.77 3665.56,3629.9 3651.22,3629.9
  region net M0_IN1: 3665,3701.92 3655,3705.47 3651.22,3684.16 3665.56,3684.16
  region net M0_IN2: 3637.79,3609.77 3639.96,3629.9 3625.62,3629.9 3627.79,3609.77
  region net M0_IN3: 3612.2,3609.77 3614.37,3629.9 3600.03,3629.9 3602.2,3609.77
  region net VDD_5V: 3586.61,3609.77 3588.78,3629.9 3574.44,3629.9 3576.61,3609.77
  region net M0_GL3: 3535.43,3609.77 3537.6,3629.9 3523.26,3629.9 3525.43,3609.77
  region net M0_GL2: 3482.67,3652.03 3497.67,3639.53 3497.67,3674.53 3482.67,3662.03
  region net $1N24400: 3752.93,3420.27 3742.33,3458.1 3727.99,3413.39 3752.93,3406.13
  region net $1N24329: 3688.98,3392.02 3691.15,3403.84 3676.81,3403.84 3678.98,3392.02
  region net $1N24724: 3663.39,3383.71 3665.56,3403.84 3651.22,3403.84 3653.39,3383.71
  region net M0_GH2: 3627.79,3472 3625.62,3458.1 3639.96,3458.1 3637.79,3472
  region net $1N24794: 3612.2,3383.71 3614.37,3403.84 3600.03,3403.84 3602.2,3383.71
  region net $1N24865: 3586.61,3383.71 3588.78,3403.84 3574.44,3403.84 3576.61,3383.71
  region net AGND: 3820.46,3604.89 3800.78,3604.89 3795.86,3586.19 3825.38,3586.19
  region net AGND: 3820.46,3579.79 3825.38,3598 3795.86,3598 3800.78,3579.79
  region net AGND: 3820.46,3630.48 3800.78,3630.48 3795.86,3611.78 3825.38,3611.78
  region net AGND: 3820.46,3604.89 3825.38,3623.59 3795.86,3623.59 3800.78,3604.89
  region net 3V3: 3284.45,3547.84 3284.45,3528.16 3313.98,3517.33 3313.98,3558.67
  region net VDD_5V: 3331.5,3664.22 3321.5,3664.22 3313.98,3649.22 3344,3649.22
  region net 3V3: 3215.55,3547.84 3186.02,3572.45 3186.02,3503.55 3215.55,3528.16
  region net $1N19388: 3974.86,3548.71 3989.86,3546.82 3989.86,3560.6 3974.86,3558.71
  region net AGND: 4014.46,3604.89 3994.78,3604.89 3989.86,3586.19 4019.38,3586.19
  region net AGND: 4014.46,3579.3 4019.38,3598 3989.86,3598 3994.78,3579.3
  region net AGND: 4014.46,3630.48 3994.78,3630.48 3989.86,3611.78 4019.38,3611.78
  region net AGND: 4014.46,3604.89 4019.38,3623.59 3989.86,3623.59 3994.78,3604.89
  region net M0_OUT3: 4194.46,3762.89 4174.78,3762.89 4169.86,3744.19 4199.38,3744.19
  region net M0_OUT3: 4194.46,3737.3 4199.38,3756 4169.86,3756 4174.78,3737.3
  region net M0_OUT3: 4194.46,3788.48 4174.78,3788.48 4169.86,3769.78 4199.38,3769.78
  region net M0_OUT3: 4194.46,3762.89 4199.38,3781.59 4169.86,3781.59 4174.78,3762.89
  region net $1N20051: 4166.05,3536.21 4180.19,3536.21 4205.38,3546.82 4175.86,3546.82
  region net AGND: 4200.46,3604.89 4180.78,3604.89 4175.86,3586.19 4205.38,3586.19
  region net AGND: 4200.46,3579.3 4205.38,3598 4175.86,3598 4180.78,3579.3
  region net AGND: 4200.46,3630.48 4180.78,3630.48 4175.86,3611.78 4205.38,3611.78
  region net AGND: 4200.46,3604.89 4205.38,3623.59 4175.86,3623.59 4180.78,3604.89
  region net M0_OUT1_N: 3986.21,3222.73 3987.26,3225.67 3975.16,3225.67 3976.21,3222.73
  region net M0_OUT1_N: 3976.21,3292.26 3974.26,3272.43 3988.16,3272.43 3986.21,3292.26
  region net M0_OUT1_P: 4001.8,3292.26 3999.85,3272.43 4013.75,3272.43 4011.8,3292.26
  region net M0_OUT1_CS: 3938.05,3491.72 3948.66,3459.57 3952.48,3509.12 3938.05,3505.87
  region net 3V3: 4032.39,3489.11 4010.49,3508.8 4010.49,3453.68 4032.39,3473.37
  region net 3V3: 4006.8,3489.11 4006.8,3473.37 4028.7,3453.68 4028.7,3508.8
  region net M0_OUT2_N: 4154.21,3207.21 4156.16,3225.09 4142.26,3225.09 4144.21,3207.21
  region net M0_OUT2_N: 4144.21,3288.26 4142.26,3268.43 4156.16,3268.43 4154.21,3288.26
  region net M0_OUT2_P: 4169.8,3288.26 4167.85,3268.43 4181.75,3268.43 4179.8,3288.26
  region net M0_OUT2_CS: 4129,3436.18 4130.56,3455.57 4116.66,3455.57 4119,3435.37
  region net 3V3: 4182.8,3487.08 4182.8,3467.4 4193.44,3455.57 4193.44,3498.91
  region net $1N24865: 3562.07,3345.32 3556.97,3354.36 3528.68,3343.75 3551.46,3317.03
  region net $1N24724: 3675,3255.88 3687.5,3270.88 3652.5,3270.88 3665,3255.88
  region net $1N24724: 3663.39,3356.75 3653.39,3356.75 3640.89,3341.75 3675.89,3341.75
  region net $1N24400: 3827,3257.88 3839.5,3272.88 3804.5,3272.88 3817,3257.88
  region net $1N24400: 3827,3344.13 3817,3344.13 3804.5,3343.75 3839.5,3343.75
  region net $1N61799: 4616.62,4137.71 4626.25,4133.2 4654.54,4143.81 4627.23,4166
  region net CP_TX: 4291.02,4475.69 4284.02,4488.19 4284.02,4453.19 4291.02,4465.69
  region net AS5600_SDA: 4204.69,4325.69 4204.69,4315.69 4205.28,4303.19 4205.28,4338.19
  region net AS5600_SCL: 4196,4277 4196,4267 4205.28,4254.5 4205.28,4288.4
  region net OLED_SCL: 4198.28,4125.69 4198.28,4115.69 4205.28,4103.19 4205.28,4138.19
  region net ESP32_BOOT: 4287.31,4025.68 4284.02,4038.18 4284.02,4003.18 4287.31,4015.68
  region net M0_IN2: 3621.72,4265.69 3621.72,4275.69 3614.72,4288.19 3614.72,4253.19
  region net M0_IN3: 3621.72,4315.69 3621.72,4325.69 3614.72,4338.19 3614.72,4303.19
  region net M0_OUT2_CS: 3621.72,4365.69 3621.72,4375.69 3614.72,4388.19 3614.72,4353.19
  region net M0_OUT1_CS: 3621.72,4415.69 3621.72,4425.69 3614.72,4438.19 3614.72,4403.19
  region net M0_OUT1_N: 4038.45,3158.12 4013.92,3195.01 4003.92,3195.01 3979.39,3158.12
  region net M0_OUT1_N: 3988.39,3160.23 3984.75,3180.83 3977.67,3187.9 3957.07,3191.55
  region net M0_OUT2_N: 4183.53,3158.04 4159,3198.93 4149,3198.93 4124.47,3158.04
  region net M0_OUT2_N: 4133.47,3160.15 4143.03,3193.96 4135.96,3201.03 4102.15,3191.47
  region net $1N8426: 3172.71,3771.68 3197.85,3765.39 3197.85,3787.98 3172.71,3781.68
  region net $1N10899: 3449.7,3704.7 3462.2,3715.39 3427.2,3715.39 3439.7,3704.7
  region net ESP32_EN: 4500.02,3922.75 4499.74,3916.81 4506.81,3909.74 4512.75,3910.02
  region net OLED_SCL: 4172.99,4180.06 4177,4167.59 4187,4167.59 4191.01,4180.06
  region net OLED_RES: 4002.32,4317.25 4008.31,4328.9 4001.24,4335.97 3989.59,4329.98
  region net OLED_RES: 4127,4289.95 4116.66,4302.41 4102.53,4302.4 4108.99,4289.94
  region net AS5600_SCL: 4157.01,4123.94 4153,4136.41 4143,4136.41 4138.99,4123.94
  region net AS5600_SDA: 4133.01,4067.94 4129,4080.41 4119,4080.41 4114.99,4067.94
  region net $1N10899: 3377.94,3678.99 3390.41,3683 3390.41,3693 3377.94,3697.01
  region net DTR: 4401.01,4119.94 4397,4132.41 4387,4132.41 4382.99,4119.94
  region net DTR: 4382.99,4104.06 4387,4091.59 4397,4091.59 4401.01,4104.06
  region net RTS: 4371.25,3972.02 4382.9,3966.03 4389.97,3973.1 4383.98,3984.75
  region net $1N5701: 4438.09,3960.18 4449.69,3955.24 4455.05,3964.02 4447.47,3975.55
  region net $1N4734: 4618.01,4169.92 4619,4185.76 4609,4194.69 4604.58,4181.92
  region net CP_TX: 4323.01,4289.94 4319,4302.41 4309,4302.41 4304.99,4289.94
  region net $1N1528: 4335.98,4223.25 4341.97,4234.9 4334.9,4241.97 4323.25,4235.98
  region net RTS: 4351.99,4386.08 4351,4370.24 4361,4361.31 4365.42,4374.08
  region net USB-PWR-DP: 4435.01,4075.94 4431,4088.41 4421,4088.41 4416.99,4075.94
  region net USB-PWR-DM: 4459.01,4049.94 4455,4062.41 4445,4062.41 4440.99,4049.94
  region net USB-PWR-DM: 4470.98,3567.92 4458.98,3563.47 4460.26,3553.47 4473.27,3550.06
  region net M0_OUT2_N: 4139.33,3334.94 4144.21,3323.44 4154.21,3328.26 4155.56,3342.75
  region net M0_OUT2_P: 4188.02,3350.75 4182.03,3339.1 4189.1,3332.03 4200.75,3338.02
  region net M0_OUT1_N: 3955.25,3342.02 3966.9,3336.03 3973.97,3343.1 3967.98,3354.75
  region net M0_OUT1_P: 4004.02,3354.75 4003.26,3348.34 4010.34,3341.26 4016.75,3342.02
  region net $1N24865: 3531.78,3308.32 3536.66,3319.91 3527.73,3325.12 3516.23,3317.4
  region net M0_GL1: 3494.99,3454.06 3499,3441.59 3509,3441.59 3513.01,3454.06
  region net $1N24794: 3619.2,3231.19 3610.74,3236.34 3603.66,3229.26 3603.19,3222.93
  region net $1N24724: 3679.56,3227.33 3675,3239.21 3665,3237.52 3661.8,3224.33
  region net $1N24329: 3775.01,3225.94 3771,3238.41 3761,3238.41 3756.99,3225.94
  region net $1N24400: 3831.01,3225.94 3827,3238.41 3817,3238.41 3812.99,3225.94
  region net M0_GH2: 3839.02,3480.93 3827.54,3485.54 3824.12,3474.8 3833.78,3463.69
  region net $1N10503: 3363.5,3874.99 3375.97,3879 3375.97,3889 3363.5,3893.01
  region net $1N8426: 3117.63,3661.55 3113,3673.34 3103,3671.35 3099.96,3658.04
  region net $1N19388: 3455.98,3517.25 3456.53,3523.46 3449.46,3530.53 3443.25,3529.98
  region net M0_IN3: 3762.75,4061.98 3751.54,4067.54 3744.46,4060.46 3750.02,4049.25
  region net M0_OUT2_CS: 3784.01,4085.92 3785,4101.76 3775,4110.69 3770.58,4097.92
  region net M0_OUT1_CS: 3821.01,4113.94 3817,4126.41 3807,4126.41 3802.99,4113.94
  region net M0_GL2: 3457.01,3587.94 3453,3600.41 3443,3600.41 3438.99,3587.94
  region net M0_GL3: 3539.89,3591.05 3535.43,3603.04 3525.43,3601.72 3522.03,3588.7
  region net M0_IN1: 3666.41,3579.99 3663.39,3593.33 3653.39,3595.36 3648.76,3583.58
  region net M0_IN1: 3733.98,3575.25 3738.7,3585.62 3731.62,3592.7 3721.25,3587.98
  region net M0_IN2: 3642.16,3614.81 3637.79,3626.9 3627.79,3625.89 3624.24,3612.99
  region net M0_IN2: 3717.01,3613.94 3713,3626.41 3703,3626.41 3698.99,3613.94
  region net M0_IN3: 3674.99,3706.06 3679,3693.59 3689,3693.59 3693.01,3706.06
  region net M0_OUT1_P: 3801.61,3754.95 3802.75,3742.48 3818.49,3742.48 3819.63,3754.95
  region net M0_OUT2_CS: 3783.25,3672.02 3790.46,3670.46 3797.54,3677.54 3795.98,3684.75
  region net M0_OUT1_CS: 3753.99,3726.08 3753,3710.24 3763,3701.31 3767.42,3714.08
  region net $1N20051: 3535.94,3492.99 3548.41,3497 3548.41,3507 3535.94,3511.01
  region net M0_OUT1_CS: 3932.1,3492.02 3943.75,3486.03 3950.82,3493.1 3944.83,3504.75
  region net M0_OUT1_CS: 3783.01,3611.94 3779,3624.41 3769,3624.41 3764.99,3611.94
  region net VDD_5V: 3335.51,3636.49 3331.5,3648.96 3321.5,3648.96 3317.5,3636.49
  region net VDD_5V: 3311.66,3676.02 3322.97,3670.37 3330.04,3677.44 3324.39,3688.75
  region net VDD_5V: 3588.98,3596.87 3586.61,3610.69 3576.61,3613.84 3571.8,3602.28
  region net 3V3: 4024.45,3490.25 4011.98,3489.11 4011.98,3473.37 4024.45,3472.23
  region net USB-PWR-DP: 4440.48,3620.53 4434.15,3621.43 4434.15,3609.62 4440.48,3610.53
  region net USB-PWR-DP: 4442.15,3571.16 4442.15,3581.16 4434.15,3582.06 4434.15,3570.25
